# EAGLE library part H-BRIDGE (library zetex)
BRIDGE
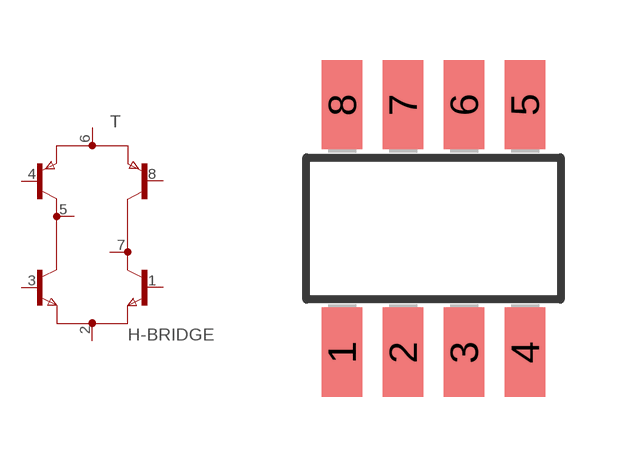
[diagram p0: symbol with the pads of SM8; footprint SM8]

Designator prefix T

## H-BRIDGE (OC_FARNELL: unknown; OC_NEWARK: unknown)  [SM8]
1  B3  pas
2  E2E3  pas
3  B2  pas
4  B1  pas
5  C1C2  pas
6  E1E4  pas
7  C3C4  pas
8  B4  pas

## Footprint SM8 (pad centres in mm)
SM8 Package
smd 1.016 x 2.235: 1 -2.286,-3.099; 2 -0.762,-3.099; 3 0.762,-3.099; 4 2.286,-3.099; 5 2.286,3.099; 6 0.762,3.099; 7 -0.762,3.099; 8 -2.286,3.099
